(* Logix 5000 project; controller EVR_Heat vendor 1 type 14 code 217 rev 35.11; software revision 35.00; part 2 of 3 *)
(* tags used below, declared in another part *)
   EVR_System_Data : System;
(* MainProgram, continued *)

ROUTINE Graco_System_Mapping   (* ladder *)
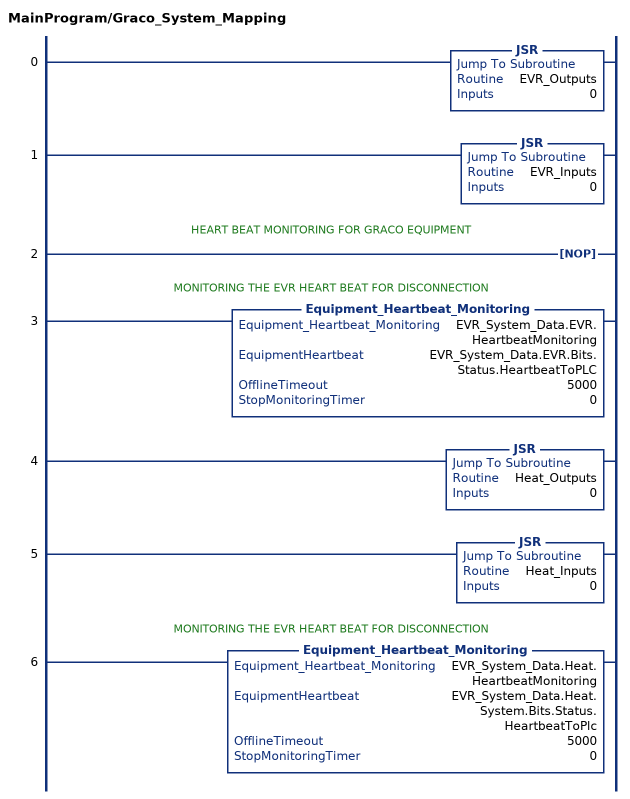
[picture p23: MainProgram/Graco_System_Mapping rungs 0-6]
   0: JSR(EVR_Outputs,0);
   1: JSR(EVR_Inputs,0);
   // HEART BEAT MONITORING FOR GRACO EQUIPMENT
   2: NOP();
   // MONITORING THE EVR HEART BEAT FOR DISCONNECTION
   3: Equipment_Heartbeat_Monitoring(EVR_System_Data.EVR.HeartbeatMonitoring,EVR_System_Data.EVR.Bits.Status.HeartbeatToPLC,5000,0);
   4: JSR(Heat_Outputs,0);
   5: JSR(Heat_Inputs,0);
   // MONITORING THE EVR HEART BEAT FOR DISCONNECTION
   6: Equipment_Heartbeat_Monitoring(EVR_System_Data.Heat.HeartbeatMonitoring,EVR_System_Data.Heat.System.Bits.Status.HeartbeatToPlc,5000,0);
END_ROUTINE

ROUTINE Heat_Inputs   (* ladder *)
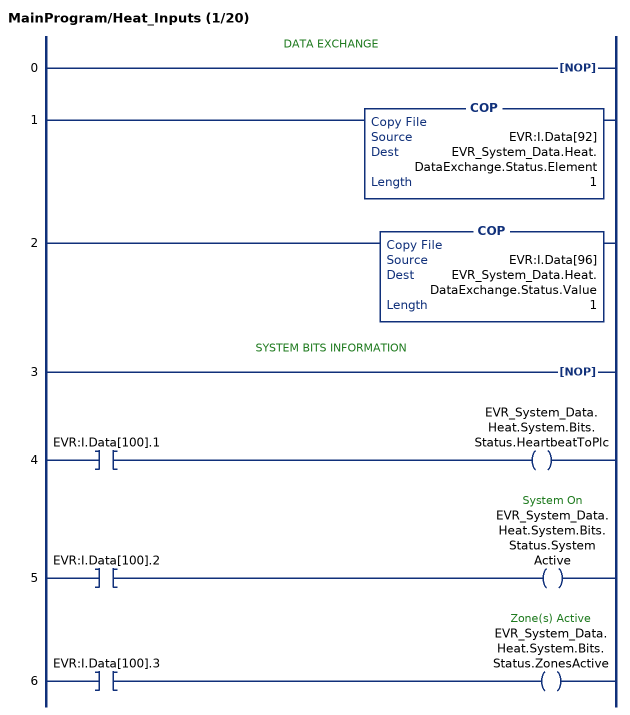
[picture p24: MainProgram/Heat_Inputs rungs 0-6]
   // DATA EXCHANGE
   0: NOP();
   1: COP(EVR:I.Data[92],EVR_System_Data.Heat.DataExchange.Status.Element,1);
   2: COP(EVR:I.Data[96],EVR_System_Data.Heat.DataExchange.Status.Value,1);
   // SYSTEM BITS INFORMATION
   3: NOP();
   4: XIC(EVR:I.Data[100].1)OTE(EVR_System_Data.Heat.System.Bits.Status.HeartbeatToPlc);
   5: XIC(EVR:I.Data[100].2)OTE(EVR_System_Data.Heat.System.Bits.Status.SystemActive);
   6: XIC(EVR:I.Data[100].3)OTE(EVR_System_Data.Heat.System.Bits.Status.ZonesActive);
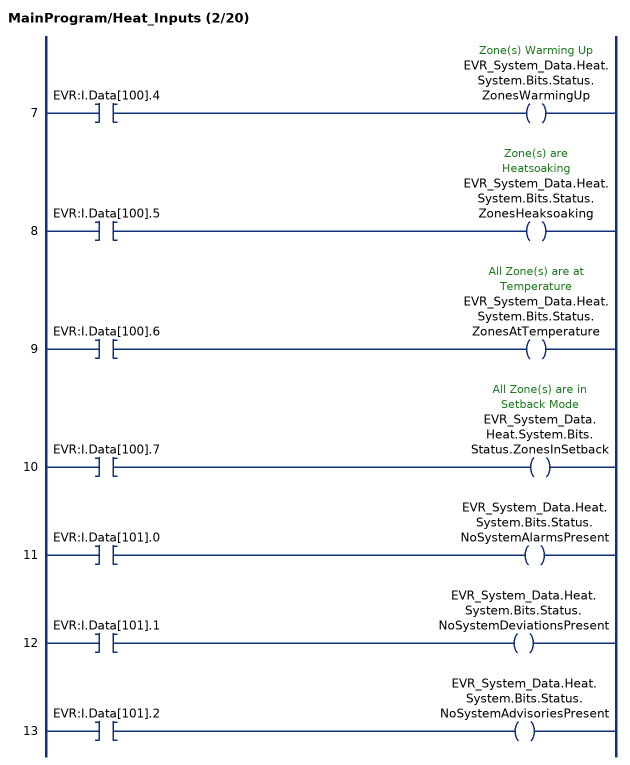
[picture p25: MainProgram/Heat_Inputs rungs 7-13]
   7: XIC(EVR:I.Data[100].4)OTE(EVR_System_Data.Heat.System.Bits.Status.ZonesWarmingUp);
   8: XIC(EVR:I.Data[100].5)OTE(EVR_System_Data.Heat.System.Bits.Status.ZonesHeaksoaking);
   9: XIC(EVR:I.Data[100].6)OTE(EVR_System_Data.Heat.System.Bits.Status.ZonesAtTemperature);
   10: XIC(EVR:I.Data[100].7)OTE(EVR_System_Data.Heat.System.Bits.Status.ZonesInSetback);
   11: XIC(EVR:I.Data[101].0)OTE(EVR_System_Data.Heat.System.Bits.Status.NoSystemAlarmsPresent);
   12: XIC(EVR:I.Data[101].1)OTE(EVR_System_Data.Heat.System.Bits.Status.NoSystemDeviationsPresent);
   13: XIC(EVR:I.Data[101].2)OTE(EVR_System_Data.Heat.System.Bits.Status.NoSystemAdvisoriesPresent);
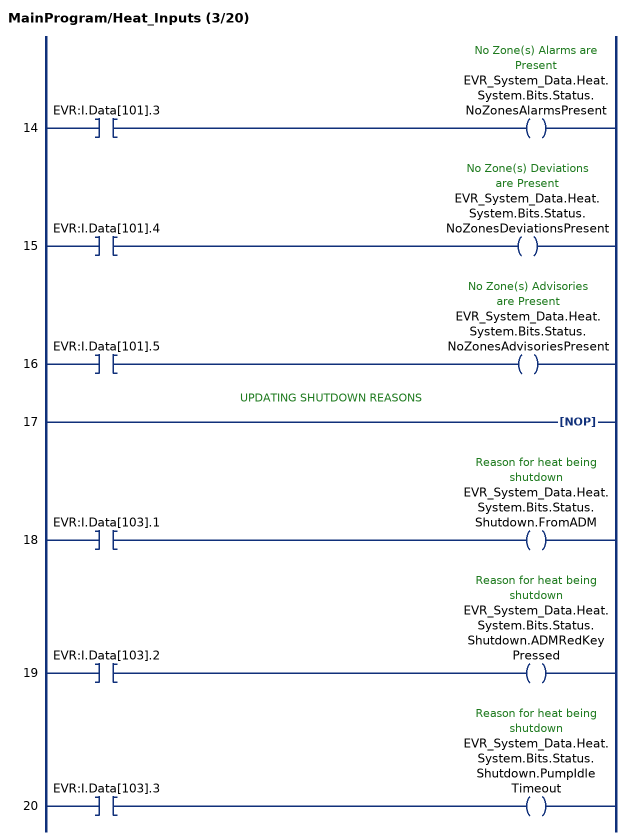
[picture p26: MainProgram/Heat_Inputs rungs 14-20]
   14: XIC(EVR:I.Data[101].3)OTE(EVR_System_Data.Heat.System.Bits.Status.NoZonesAlarmsPresent);
   15: XIC(EVR:I.Data[101].4)OTE(EVR_System_Data.Heat.System.Bits.Status.NoZonesDeviationsPresent);
   16: XIC(EVR:I.Data[101].5)OTE(EVR_System_Data.Heat.System.Bits.Status.NoZonesAdvisoriesPresent);
   // UPDATING SHUTDOWN REASONS
   17: NOP();
   18: XIC(EVR:I.Data[103].1)OTE(EVR_System_Data.Heat.System.Bits.Status.Shutdown.FromADM);
   19: XIC(EVR:I.Data[103].2)OTE(EVR_System_Data.Heat.System.Bits.Status.Shutdown.ADMRedKeyPressed);
   20: XIC(EVR:I.Data[103].3)OTE(EVR_System_Data.Heat.System.Bits.Status.Shutdown.PumpIdleTimeout);
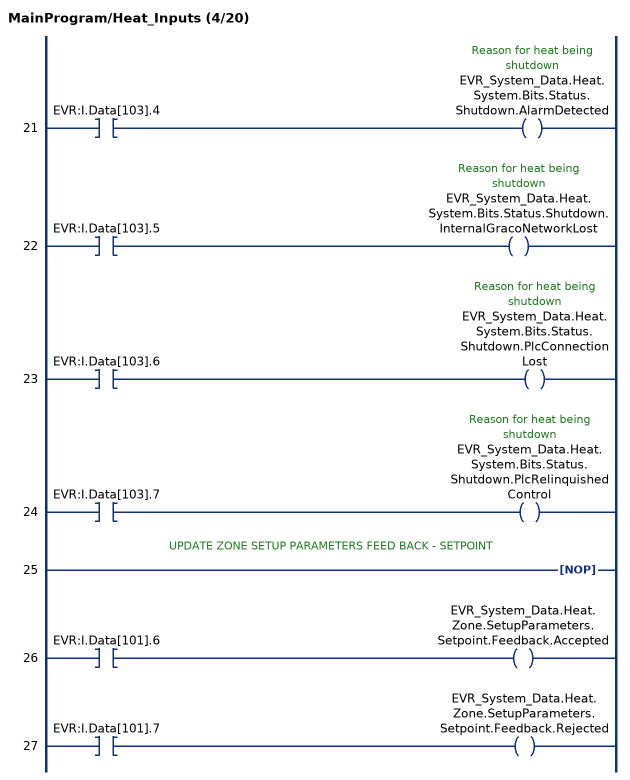
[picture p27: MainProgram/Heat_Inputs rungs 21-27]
   21: XIC(EVR:I.Data[103].4)OTE(EVR_System_Data.Heat.System.Bits.Status.Shutdown.AlarmDetected);
   22: XIC(EVR:I.Data[103].5)OTE(EVR_System_Data.Heat.System.Bits.Status.Shutdown.InternalGracoNetworkLost);
   23: XIC(EVR:I.Data[103].6)OTE(EVR_System_Data.Heat.System.Bits.Status.Shutdown.PlcConnectionLost);
   24: XIC(EVR:I.Data[103].7)OTE(EVR_System_Data.Heat.System.Bits.Status.Shutdown.PlcRelinquishedControl);
   // UPDATE ZONE SETUP PARAMETERS FEED BACK - SETPOINT
   25: NOP();
   26: XIC(EVR:I.Data[101].6)OTE(EVR_System_Data.Heat.Zone.SetupParameters.Setpoint.Feedback.Accepted);
   27: XIC(EVR:I.Data[101].7)OTE(EVR_System_Data.Heat.Zone.SetupParameters.Setpoint.Feedback.Rejected);
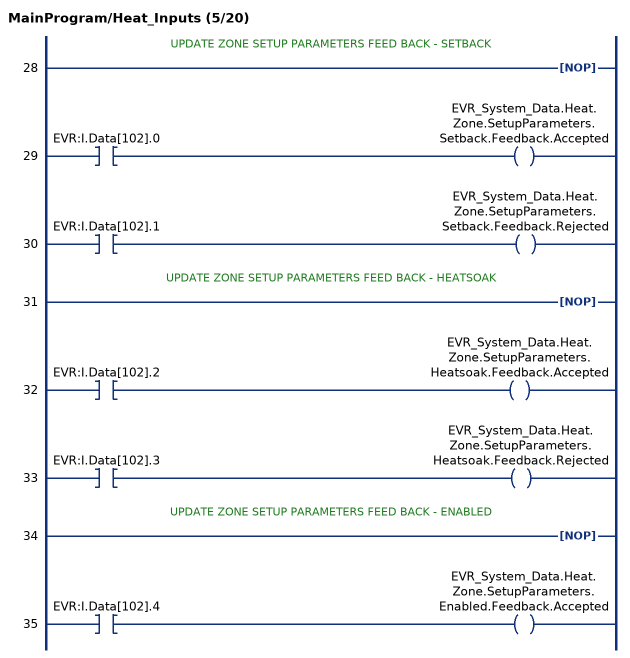
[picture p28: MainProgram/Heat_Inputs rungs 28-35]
   // UPDATE ZONE SETUP PARAMETERS FEED BACK - SETBACK
   28: NOP();
   29: XIC(EVR:I.Data[102].0)OTE(EVR_System_Data.Heat.Zone.SetupParameters.Setback.Feedback.Accepted);
   30: XIC(EVR:I.Data[102].1)OTE(EVR_System_Data.Heat.Zone.SetupParameters.Setback.Feedback.Rejected);
   // UPDATE ZONE SETUP PARAMETERS FEED BACK - HEATSOAK
   31: NOP();
   32: XIC(EVR:I.Data[102].2)OTE(EVR_System_Data.Heat.Zone.SetupParameters.Heatsoak.Feedback.Accepted);
   33: XIC(EVR:I.Data[102].3)OTE(EVR_System_Data.Heat.Zone.SetupParameters.Heatsoak.Feedback.Rejected);
   // UPDATE ZONE SETUP PARAMETERS FEED BACK - ENABLED
   34: NOP();
   35: XIC(EVR:I.Data[102].4)OTE(EVR_System_Data.Heat.Zone.SetupParameters.Enabled.Feedback.Accepted);
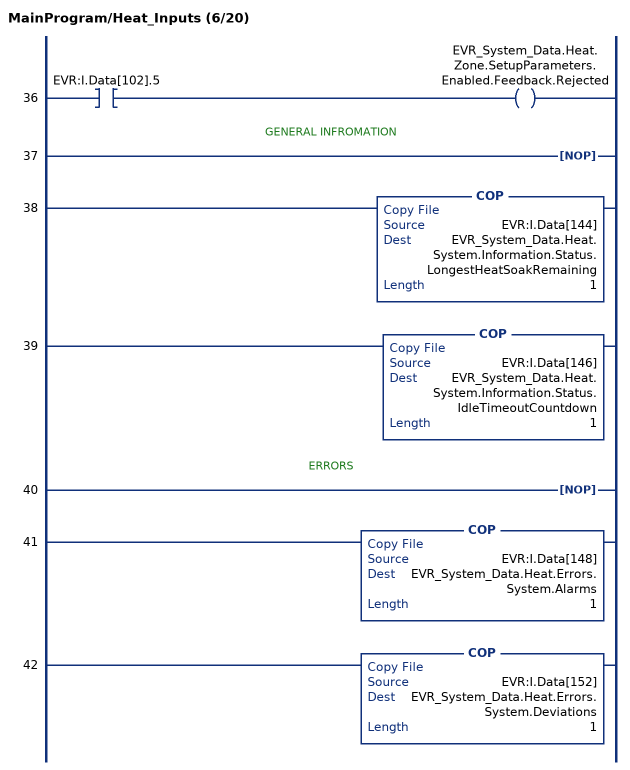
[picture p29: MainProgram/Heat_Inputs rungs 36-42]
   36: XIC(EVR:I.Data[102].5)OTE(EVR_System_Data.Heat.Zone.SetupParameters.Enabled.Feedback.Rejected);
   // GENERAL INFROMATION
   37: NOP();
   38: COP(EVR:I.Data[144],EVR_System_Data.Heat.System.Information.Status.LongestHeatSoakRemaining,1);
   39: COP(EVR:I.Data[146],EVR_System_Data.Heat.System.Information.Status.IdleTimeoutCountdown,1);
   // ERRORS
   40: NOP();
   41: COP(EVR:I.Data[148],EVR_System_Data.Heat.Errors.System.Alarms,1);
   42: COP(EVR:I.Data[152],EVR_System_Data.Heat.Errors.System.Deviations,1);
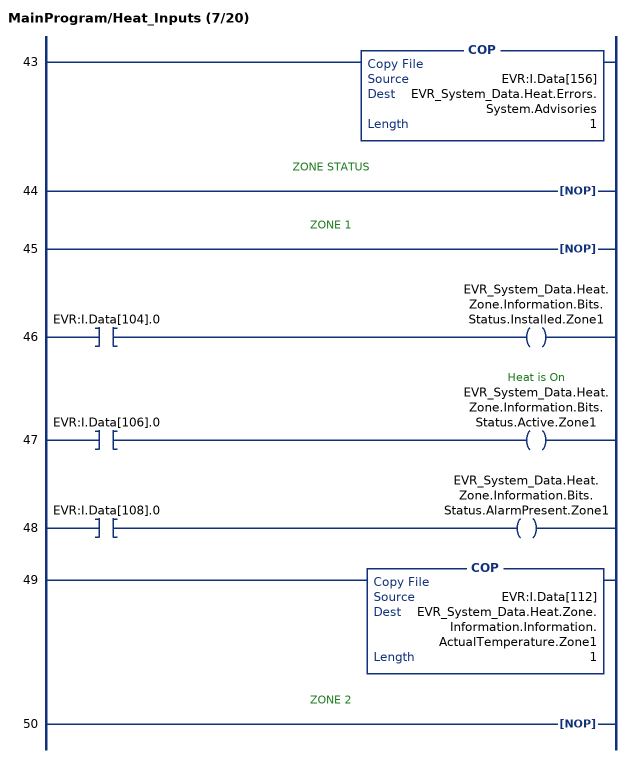
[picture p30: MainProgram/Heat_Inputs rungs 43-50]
   43: COP(EVR:I.Data[156],EVR_System_Data.Heat.Errors.System.Advisories,1);
   // ZONE STATUS
   44: NOP();
   // ZONE 1
   45: NOP();
   46: XIC(EVR:I.Data[104].0)OTE(EVR_System_Data.Heat.Zone.Information.Bits.Status.Installed.Zone1);
   47: XIC(EVR:I.Data[106].0)OTE(EVR_System_Data.Heat.Zone.Information.Bits.Status.Active.Zone1);
   48: XIC(EVR:I.Data[108].0)OTE(EVR_System_Data.Heat.Zone.Information.Bits.Status.AlarmPresent.Zone1);
   49: COP(EVR:I.Data[112],EVR_System_Data.Heat.Zone.Information.Information.ActualTemperature.Zone1,1);
   // ZONE 2
   50: NOP();
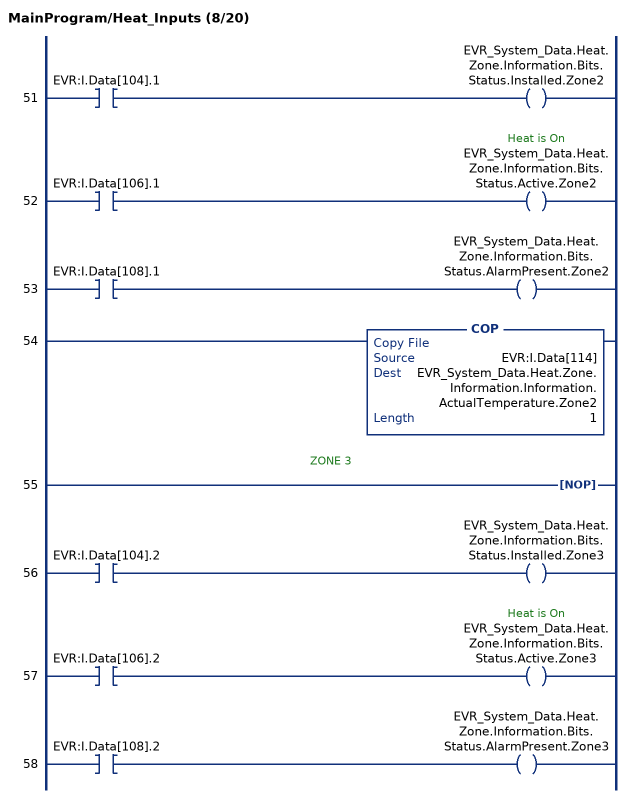
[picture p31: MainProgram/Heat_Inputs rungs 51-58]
   51: XIC(EVR:I.Data[104].1)OTE(EVR_System_Data.Heat.Zone.Information.Bits.Status.Installed.Zone2);
   52: XIC(EVR:I.Data[106].1)OTE(EVR_System_Data.Heat.Zone.Information.Bits.Status.Active.Zone2);
   53: XIC(EVR:I.Data[108].1)OTE(EVR_System_Data.Heat.Zone.Information.Bits.Status.AlarmPresent.Zone2);
   54: COP(EVR:I.Data[114],EVR_System_Data.Heat.Zone.Information.Information.ActualTemperature.Zone2,1);
   // ZONE 3
   55: NOP();
   56: XIC(EVR:I.Data[104].2)OTE(EVR_System_Data.Heat.Zone.Information.Bits.Status.Installed.Zone3);
   57: XIC(EVR:I.Data[106].2)OTE(EVR_System_Data.Heat.Zone.Information.Bits.Status.Active.Zone3);
   58: XIC(EVR:I.Data[108].2)OTE(EVR_System_Data.Heat.Zone.Information.Bits.Status.AlarmPresent.Zone3);
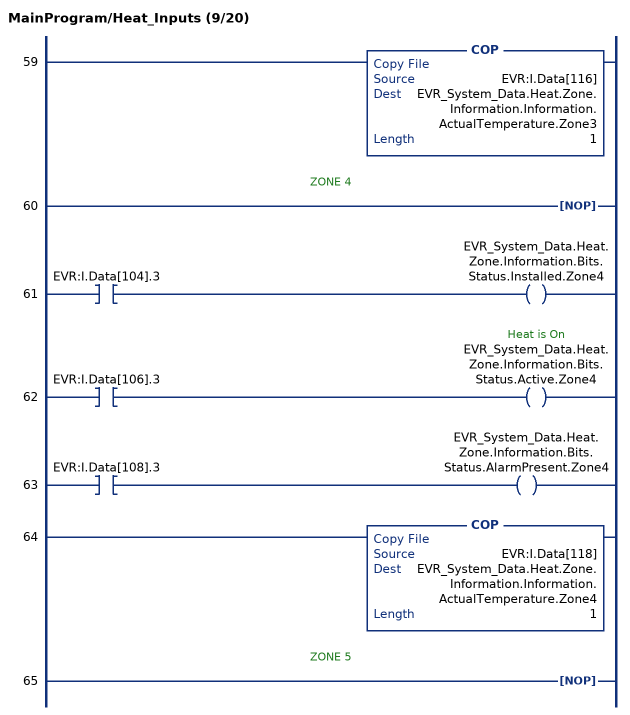
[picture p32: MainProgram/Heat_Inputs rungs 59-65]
   59: COP(EVR:I.Data[116],EVR_System_Data.Heat.Zone.Information.Information.ActualTemperature.Zone3,1);
   // ZONE 4
   60: NOP();
   61: XIC(EVR:I.Data[104].3)OTE(EVR_System_Data.Heat.Zone.Information.Bits.Status.Installed.Zone4);
   62: XIC(EVR:I.Data[106].3)OTE(EVR_System_Data.Heat.Zone.Information.Bits.Status.Active.Zone4);
   63: XIC(EVR:I.Data[108].3)OTE(EVR_System_Data.Heat.Zone.Information.Bits.Status.AlarmPresent.Zone4);
   64: COP(EVR:I.Data[118],EVR_System_Data.Heat.Zone.Information.Information.ActualTemperature.Zone4,1);
   // ZONE 5
   65: NOP();
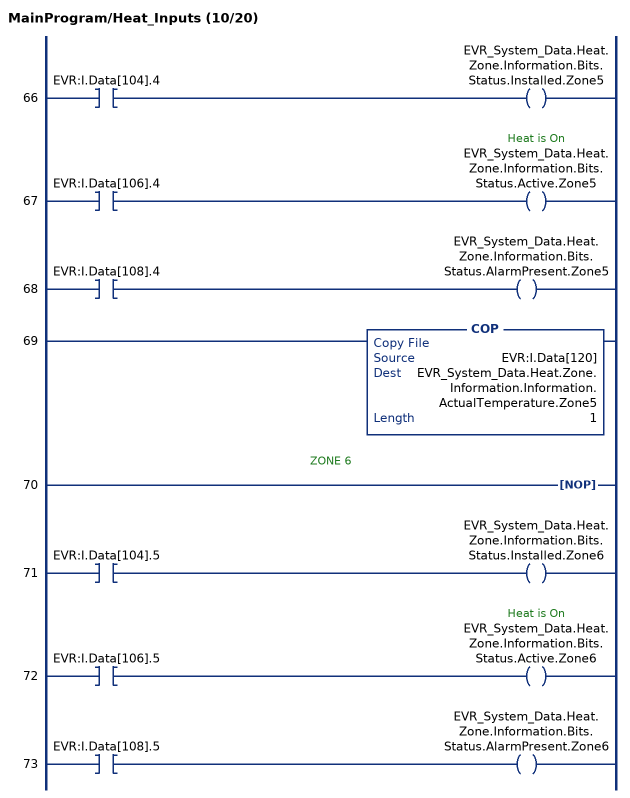
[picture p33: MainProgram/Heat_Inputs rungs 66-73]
   66: XIC(EVR:I.Data[104].4)OTE(EVR_System_Data.Heat.Zone.Information.Bits.Status.Installed.Zone5);
   67: XIC(EVR:I.Data[106].4)OTE(EVR_System_Data.Heat.Zone.Information.Bits.Status.Active.Zone5);
   68: XIC(EVR:I.Data[108].4)OTE(EVR_System_Data.Heat.Zone.Information.Bits.Status.AlarmPresent.Zone5);
   69: COP(EVR:I.Data[120],EVR_System_Data.Heat.Zone.Information.Information.ActualTemperature.Zone5,1);
   // ZONE 6
   70: NOP();
   71: XIC(EVR:I.Data[104].5)OTE(EVR_System_Data.Heat.Zone.Information.Bits.Status.Installed.Zone6);
   72: XIC(EVR:I.Data[106].5)OTE(EVR_System_Data.Heat.Zone.Information.Bits.Status.Active.Zone6);
   73: XIC(EVR:I.Data[108].5)OTE(EVR_System_Data.Heat.Zone.Information.Bits.Status.AlarmPresent.Zone6);
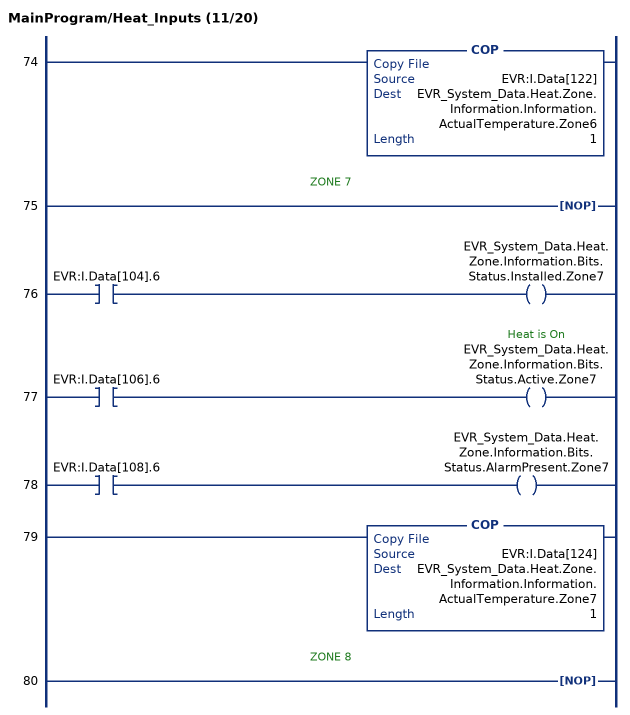
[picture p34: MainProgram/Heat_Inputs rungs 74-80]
   74: COP(EVR:I.Data[122],EVR_System_Data.Heat.Zone.Information.Information.ActualTemperature.Zone6,1);
   // ZONE 7
   75: NOP();
   76: XIC(EVR:I.Data[104].6)OTE(EVR_System_Data.Heat.Zone.Information.Bits.Status.Installed.Zone7);
   77: XIC(EVR:I.Data[106].6)OTE(EVR_System_Data.Heat.Zone.Information.Bits.Status.Active.Zone7);
   78: XIC(EVR:I.Data[108].6)OTE(EVR_System_Data.Heat.Zone.Information.Bits.Status.AlarmPresent.Zone7);
   79: COP(EVR:I.Data[124],EVR_System_Data.Heat.Zone.Information.Information.ActualTemperature.Zone7,1);
   // ZONE 8
   80: NOP();
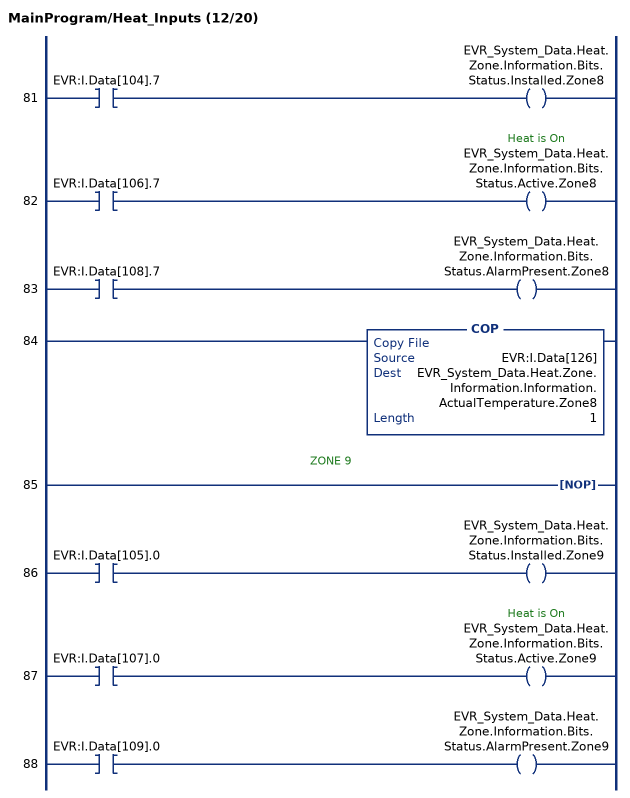
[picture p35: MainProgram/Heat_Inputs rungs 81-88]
   81: XIC(EVR:I.Data[104].7)OTE(EVR_System_Data.Heat.Zone.Information.Bits.Status.Installed.Zone8);
   82: XIC(EVR:I.Data[106].7)OTE(EVR_System_Data.Heat.Zone.Information.Bits.Status.Active.Zone8);
   83: XIC(EVR:I.Data[108].7)OTE(EVR_System_Data.Heat.Zone.Information.Bits.Status.AlarmPresent.Zone8);
   84: COP(EVR:I.Data[126],EVR_System_Data.Heat.Zone.Information.Information.ActualTemperature.Zone8,1);
   // ZONE 9
   85: NOP();
   86: XIC(EVR:I.Data[105].0)OTE(EVR_System_Data.Heat.Zone.Information.Bits.Status.Installed.Zone9);
   87: XIC(EVR:I.Data[107].0)OTE(EVR_System_Data.Heat.Zone.Information.Bits.Status.Active.Zone9);
   88: XIC(EVR:I.Data[109].0)OTE(EVR_System_Data.Heat.Zone.Information.Bits.Status.AlarmPresent.Zone9);
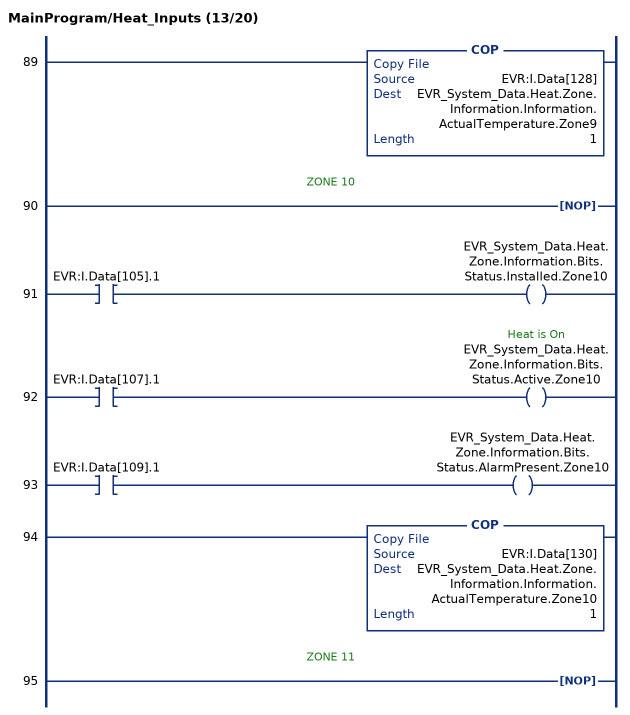
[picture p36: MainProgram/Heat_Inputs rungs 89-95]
   89: COP(EVR:I.Data[128],EVR_System_Data.Heat.Zone.Information.Information.ActualTemperature.Zone9,1);
   // ZONE 10
   90: NOP();
   91: XIC(EVR:I.Data[105].1)OTE(EVR_System_Data.Heat.Zone.Information.Bits.Status.Installed.Zone10);
   92: XIC(EVR:I.Data[107].1)OTE(EVR_System_Data.Heat.Zone.Information.Bits.Status.Active.Zone10);
   93: XIC(EVR:I.Data[109].1)OTE(EVR_System_Data.Heat.Zone.Information.Bits.Status.AlarmPresent.Zone10);
   94: COP(EVR:I.Data[130],EVR_System_Data.Heat.Zone.Information.Information.ActualTemperature.Zone10,1);
   // ZONE 11
   95: NOP();
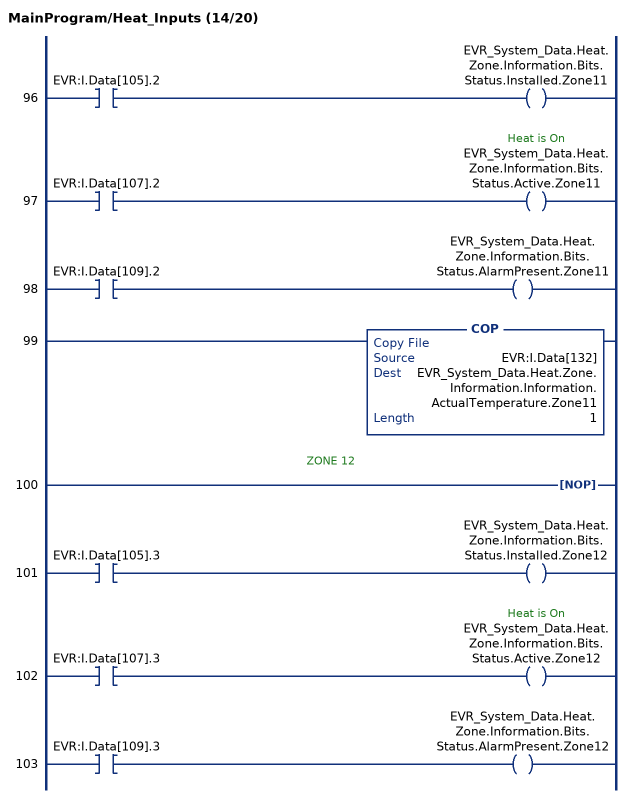
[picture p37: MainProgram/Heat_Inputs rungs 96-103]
   96: XIC(EVR:I.Data[105].2)OTE(EVR_System_Data.Heat.Zone.Information.Bits.Status.Installed.Zone11);
   97: XIC(EVR:I.Data[107].2)OTE(EVR_System_Data.Heat.Zone.Information.Bits.Status.Active.Zone11);
   98: XIC(EVR:I.Data[109].2)OTE(EVR_System_Data.Heat.Zone.Information.Bits.Status.AlarmPresent.Zone11);
   99: COP(EVR:I.Data[132],EVR_System_Data.Heat.Zone.Information.Information.ActualTemperature.Zone11,1);
   // ZONE 12
   100: NOP();
   101: XIC(EVR:I.Data[105].3)OTE(EVR_System_Data.Heat.Zone.Information.Bits.Status.Installed.Zone12);
   102: XIC(EVR:I.Data[107].3)OTE(EVR_System_Data.Heat.Zone.Information.Bits.Status.Active.Zone12);
   103: XIC(EVR:I.Data[109].3)OTE(EVR_System_Data.Heat.Zone.Information.Bits.Status.AlarmPresent.Zone12);
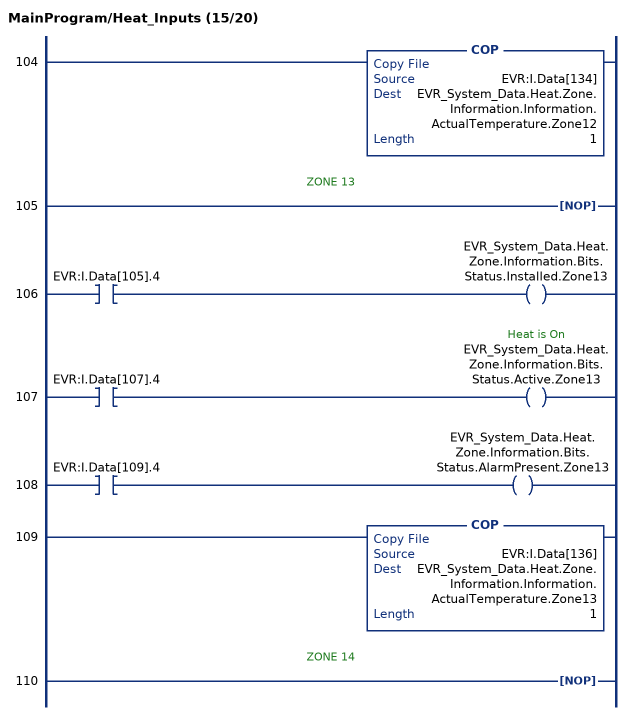
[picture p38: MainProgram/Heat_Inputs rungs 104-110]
   104: COP(EVR:I.Data[134],EVR_System_Data.Heat.Zone.Information.Information.ActualTemperature.Zone12,1);
   // ZONE 13
   105: NOP();
   106: XIC(EVR:I.Data[105].4)OTE(EVR_System_Data.Heat.Zone.Information.Bits.Status.Installed.Zone13);
   107: XIC(EVR:I.Data[107].4)OTE(EVR_System_Data.Heat.Zone.Information.Bits.Status.Active.Zone13);
   108: XIC(EVR:I.Data[109].4)OTE(EVR_System_Data.Heat.Zone.Information.Bits.Status.AlarmPresent.Zone13);
   109: COP(EVR:I.Data[136],EVR_System_Data.Heat.Zone.Information.Information.ActualTemperature.Zone13,1);
   // ZONE 14
   110: NOP();
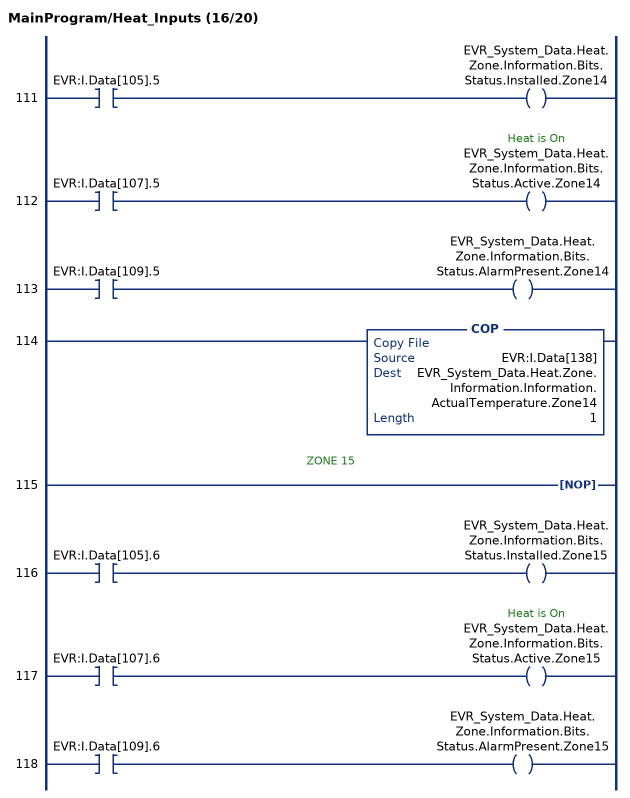
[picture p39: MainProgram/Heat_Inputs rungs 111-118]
   111: XIC(EVR:I.Data[105].5)OTE(EVR_System_Data.Heat.Zone.Information.Bits.Status.Installed.Zone14);
   112: XIC(EVR:I.Data[107].5)OTE(EVR_System_Data.Heat.Zone.Information.Bits.Status.Active.Zone14);
   113: XIC(EVR:I.Data[109].5)OTE(EVR_System_Data.Heat.Zone.Information.Bits.Status.AlarmPresent.Zone14);
   114: COP(EVR:I.Data[138],EVR_System_Data.Heat.Zone.Information.Information.ActualTemperature.Zone14,1);
   // ZONE 15
   115: NOP();
   116: XIC(EVR:I.Data[105].6)OTE(EVR_System_Data.Heat.Zone.Information.Bits.Status.Installed.Zone15);
   117: XIC(EVR:I.Data[107].6)OTE(EVR_System_Data.Heat.Zone.Information.Bits.Status.Active.Zone15);
   118: XIC(EVR:I.Data[109].6)OTE(EVR_System_Data.Heat.Zone.Information.Bits.Status.AlarmPresent.Zone15);
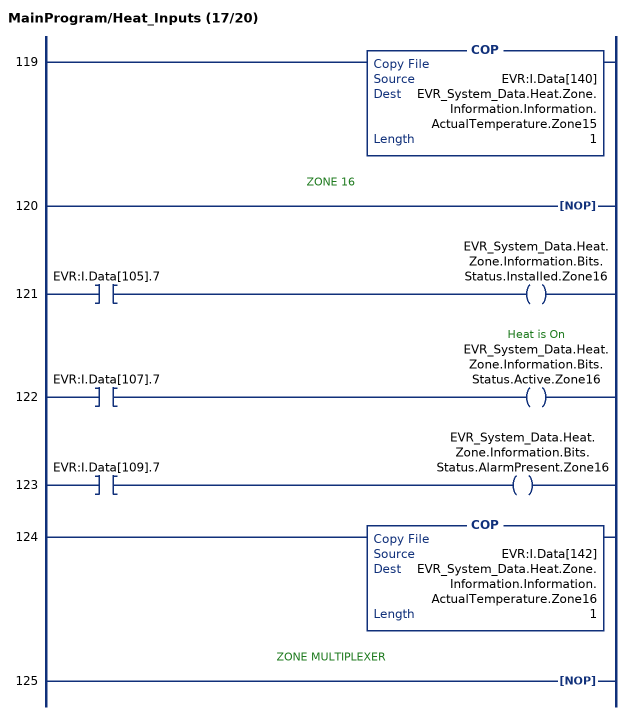
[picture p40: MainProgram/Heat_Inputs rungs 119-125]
   119: COP(EVR:I.Data[140],EVR_System_Data.Heat.Zone.Information.Information.ActualTemperature.Zone15,1);
   // ZONE 16
   120: NOP();
   121: XIC(EVR:I.Data[105].7)OTE(EVR_System_Data.Heat.Zone.Information.Bits.Status.Installed.Zone16);
   122: XIC(EVR:I.Data[107].7)OTE(EVR_System_Data.Heat.Zone.Information.Bits.Status.Active.Zone16);
   123: XIC(EVR:I.Data[109].7)OTE(EVR_System_Data.Heat.Zone.Information.Bits.Status.AlarmPresent.Zone16);
   124: COP(EVR:I.Data[142],EVR_System_Data.Heat.Zone.Information.Information.ActualTemperature.Zone16,1);
   // ZONE MULTIPLEXER
   125: NOP();
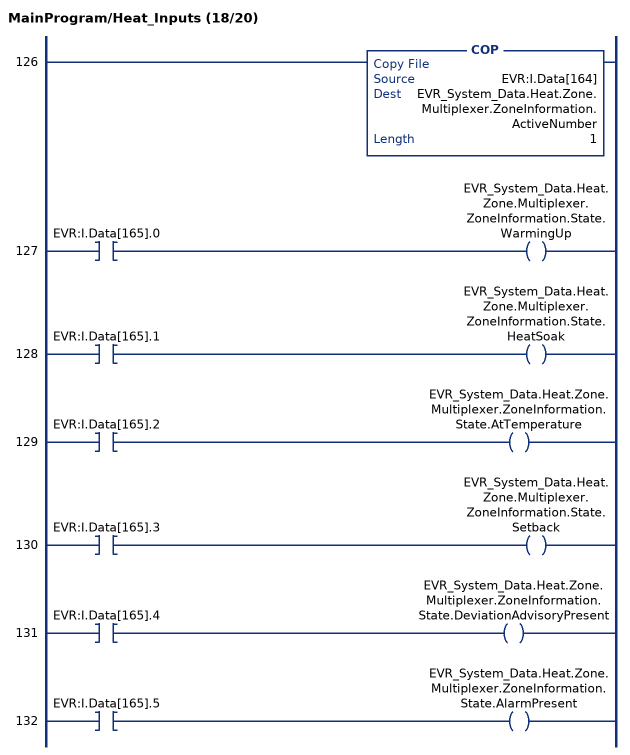
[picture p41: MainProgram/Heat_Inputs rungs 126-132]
   126: COP(EVR:I.Data[164],EVR_System_Data.Heat.Zone.Multiplexer.ZoneInformation.ActiveNumber,1);
   127: XIC(EVR:I.Data[165].0)OTE(EVR_System_Data.Heat.Zone.Multiplexer.ZoneInformation.State.WarmingUp);
   128: XIC(EVR:I.Data[165].1)OTE(EVR_System_Data.Heat.Zone.Multiplexer.ZoneInformation.State.HeatSoak);
   129: XIC(EVR:I.Data[165].2)OTE(EVR_System_Data.Heat.Zone.Multiplexer.ZoneInformation.State.AtTemperature);
   130: XIC(EVR:I.Data[165].3)OTE(EVR_System_Data.Heat.Zone.Multiplexer.ZoneInformation.State.Setback);
   131: XIC(EVR:I.Data[165].4)OTE(EVR_System_Data.Heat.Zone.Multiplexer.ZoneInformation.State.DeviationAdvisoryPresent);
   132: XIC(EVR:I.Data[165].5)OTE(EVR_System_Data.Heat.Zone.Multiplexer.ZoneInformation.State.AlarmPresent);
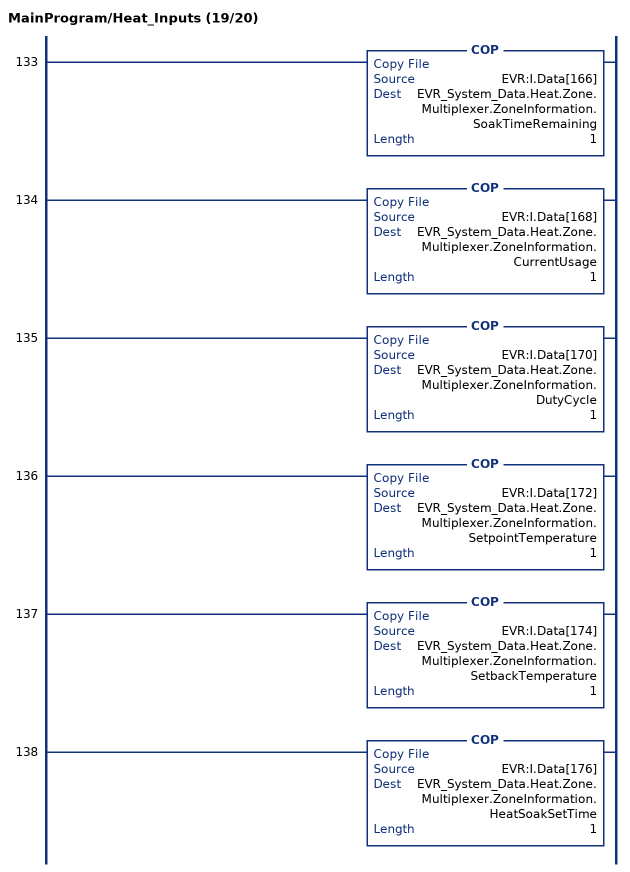
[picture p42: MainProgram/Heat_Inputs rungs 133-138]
   133: COP(EVR:I.Data[166],EVR_System_Data.Heat.Zone.Multiplexer.ZoneInformation.SoakTimeRemaining,1);
   134: COP(EVR:I.Data[168],EVR_System_Data.Heat.Zone.Multiplexer.ZoneInformation.CurrentUsage,1);
   135: COP(EVR:I.Data[170],EVR_System_Data.Heat.Zone.Multiplexer.ZoneInformation.DutyCycle,1);
   136: COP(EVR:I.Data[172],EVR_System_Data.Heat.Zone.Multiplexer.ZoneInformation.SetpointTemperature,1);
   137: COP(EVR:I.Data[174],EVR_System_Data.Heat.Zone.Multiplexer.ZoneInformation.SetbackTemperature,1);
   138: COP(EVR:I.Data[176],EVR_System_Data.Heat.Zone.Multiplexer.ZoneInformation.HeatSoakSetTime,1);
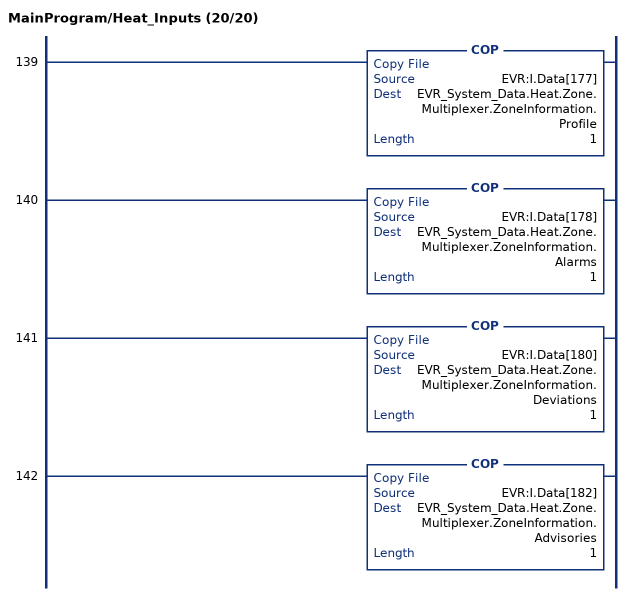
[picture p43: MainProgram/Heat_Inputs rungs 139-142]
   139: COP(EVR:I.Data[177],EVR_System_Data.Heat.Zone.Multiplexer.ZoneInformation.Profile,1);
   140: COP(EVR:I.Data[178],EVR_System_Data.Heat.Zone.Multiplexer.ZoneInformation.Alarms,1);
   141: COP(EVR:I.Data[180],EVR_System_Data.Heat.Zone.Multiplexer.ZoneInformation.Deviations,1);
   142: COP(EVR:I.Data[182],EVR_System_Data.Heat.Zone.Multiplexer.ZoneInformation.Advisories,1);
END_ROUTINE
